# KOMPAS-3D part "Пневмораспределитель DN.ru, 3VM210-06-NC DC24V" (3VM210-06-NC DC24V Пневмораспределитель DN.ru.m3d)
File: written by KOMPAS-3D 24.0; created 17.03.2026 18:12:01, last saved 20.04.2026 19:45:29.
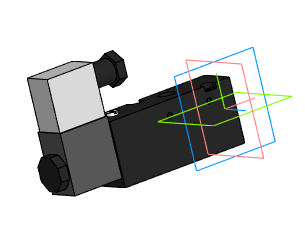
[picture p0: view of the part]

Document properties: Автор: R2D2; Полное имя файла: ..\AC24V\3VM210-06-NC AC24V Пневмораспредели тель DN.ru.cdw

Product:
- Part/product: Пневмораспределитель DN.ru  | designation 3VM210-06-NC DC24V
    Масса: 0.3
    Раздел спецификации: Прочие изделия
    Форматы листов документа: A3
    Примечание: D290-00377

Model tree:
1. Операция без истории:3

Expressions: 3VM210-06-NC DC24V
